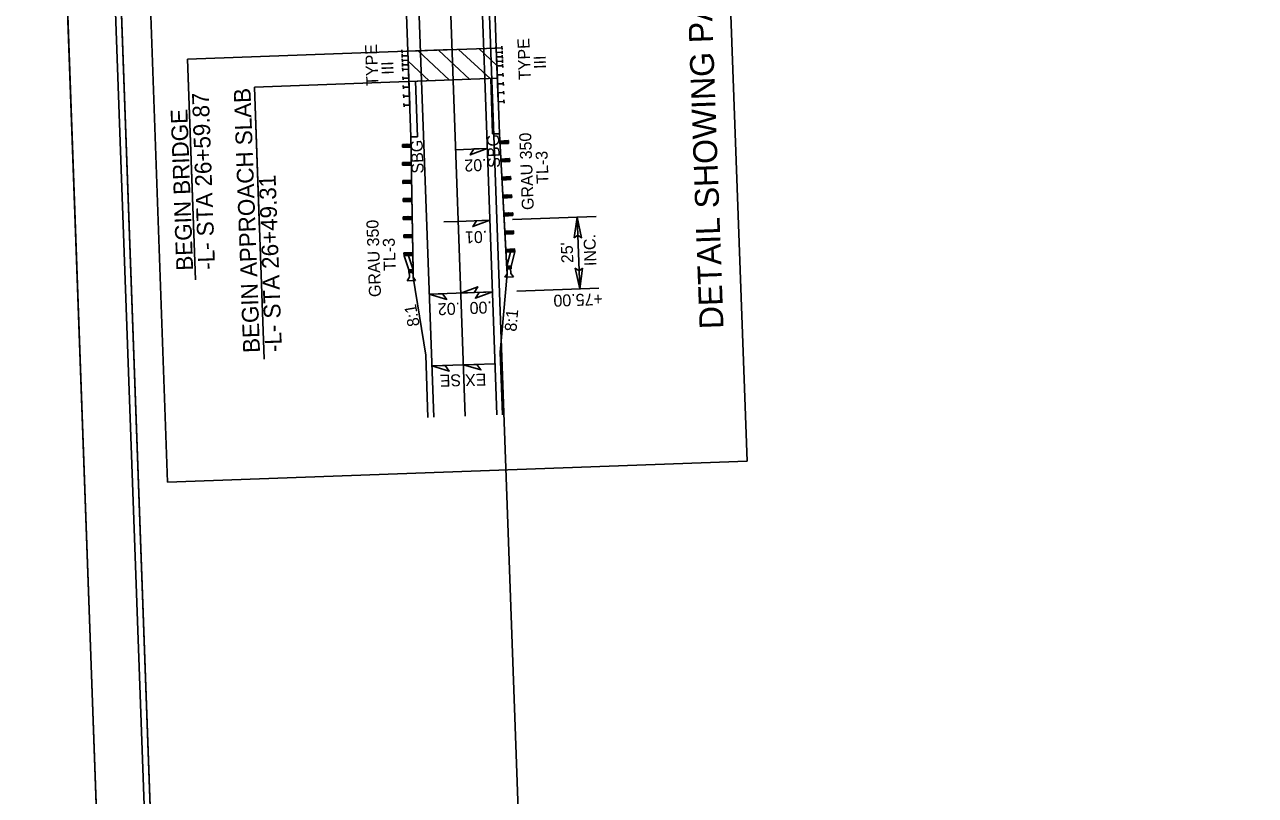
# Model space of a CAD drawing. Extents: x 2065256 to 2066537, y 145527 to 147314.
# Drawn here: x 2065382 to 2065896, y 146420 to 146742 of the extents above; entities that cross this region are included whole.
import ezdxf

# ---------------------------------------------------------------- set-up
doc = ezdxf.new("R2010")
doc.units = 0
for name, color, linetype in [('Prop Approach Slab', 7, 'Continuous'), ('Prop Approach Slab Hatching', 7, 'Continuous'), ('Prop Conc Shoulder Berm Gutter', 7, 'Continuous'), ('Prop Dimension', 7, 'Continuous'), ('Prop Dimension Text', 7, 'Continuous'), ('Prop EOT', 7, 'Continuous'), ('Prop Guardrail', 7, 'Continuous'), ('Prop Guardrail Anchor Unit CELL', 7, 'Continuous'), ('Prop Horizontal Alignment', 7, 'Continuous'), ('Prop Horizontal Alignment Station Label', 7, 'Continuous'), ('Prop Horizontal Alignment Tick Small', 7, 'Continuous'), ('Prop Paved Shoulder', 7, 'Continuous'), ('Prop Roadway Bridge', 7, 'Continuous'), ('Prop Structure Anchor Unit CELL', 7, 'Continuous'), ('Prop Superelevation  Arrow CELL', 7, 'Continuous'), ('Prop Superelevation Label', 7, 'Continuous'), ('Prop Terminator CELL', 7, 'Continuous'), ('Sheet Clip Boundary CELL', 7, 'Continuous'), ('Sheet Cutting Line CELL', 7, 'Continuous'), ('Sheet Layout Plan Border', 7, 'Continuous'), ('Sheet Plan CELL', 7, 'Continuous'), ('Sheet Plan Layout CELL', 7, 'Continuous'), ('Sheet Plot Border Inside CELL', 7, 'Continuous'), ('Sheet Plot Border Outside CELL', 7, 'Continuous')]:
    doc.layers.add(name, color=color, linetype=linetype)

# ---------------------------------------------------------------- blocks, each defined once
blk = doc.blocks.new('Super Arrow Terminator')
at = {"layer": 'Prop Superelevation  Arrow CELL'}
blk.add_lwpolyline([(0, 0), (-6, -2), (-4.625, 0)], close=True, dxfattribs=at)

msp = doc.modelspace()

# ---------------------------------------------------------------- linework, layer by layer
at = {"layer": 'Prop Approach Slab'}
for p, q in [((2065542.53, 146718.66), (2065542.07, 146731.33)), ((2065579.5, 146720), (2065579.04, 146732.66)), ((2065542.53, 146718.66), (2065579.5, 146720))]:
    msp.add_line(p, q, dxfattribs=at)
at = {"layer": 'Prop Approach Slab Hatching'}
for p, q in [((2065559.48, 146719.28), (2065546.36, 146731.48)), ((2065567.96, 146719.58), (2065554.84, 146731.79)), ((2065576.44, 146719.89), (2065563.32, 146732.1)), ((2065579.31, 146725.42), (2065571.8, 146732.4)), ((2065579.04, 146732.75), (2065578.58, 146733.18)), ((2065551.01, 146718.97), (2065542.22, 146727.14))]:
    msp.add_line(p, q, dxfattribs=at)
at = {"layer": 'Prop Conc Shoulder Berm Gutter'}
for p, q in [((2065546.16, 146695.61), (2065545.32, 146718.76)), ((2065577.54, 146696.74), (2065576.71, 146719.9))]:
    msp.add_line(p, q, dxfattribs=at)
at = {"layer": 'Prop Dimension'}
for p, q in [((2065683.84, 146559.92), (2065666.92, 147028.09)), ((2065441.7, 146551.17), (2065424.78, 147019.34)), ((2065620.8, 146662.28), (2065585.78, 146661.02)), ((2065613.91, 146632.01), (2065612.83, 146661.99)), ((2065621.88, 146632.3), (2065587.66, 146631.07)), ((2065683.84, 146559.92), (2065441.7, 146551.17))]:
    msp.add_line(p, q, dxfattribs=at)
at = {"layer": 'Prop EOT'}
for p, q in [((2065547.82, 146718.86), (2065537.68, 146999.49)), ((2065574.2, 146719.81), (2065564.06, 147000.44)), ((2065552.9, 146578.33), (2065547.82, 146719.01)), ((2065579.28, 146579.28), (2065574.2, 146719.96)), ((2065577.54, 146696.74), (2065580.34, 146696.84))]:
    msp.add_line(p, q, dxfattribs=at)
at = {"layer": 'Prop Guardrail'}
for p, q in [((2065542.81, 146710.8), (2065543.08, 146703.3)), ((2065580.06, 146704.64), (2065579.79, 146712.13))]:
    msp.add_line(p, q, dxfattribs=at)
at = {"layer": 'Prop Guardrail Anchor Unit CELL'}
for p, q in [((2065543.36, 146695.51), (2065544.27, 146639.41)), ((2065580.34, 146696.84), (2065583.49, 146640.83)), ((2065543.41, 146692.46), (2065539.81, 146692.4)), ((2065541.63, 146691.23), (2065539.81, 146692.4)), ((2065539.81, 146692.4), (2065539.83, 146691.2)), ((2065539.83, 146691.2), (2065541.61, 146692.43)), ((2065543.43, 146691.26), (2065539.83, 146691.2)), ((2065541.61, 146692.43), (2065541.63, 146691.23)), ((2065541.61, 146692.43), (2065543.43, 146691.26)), ((2065541.63, 146691.23), (2065543.41, 146692.46)), ((2065543.43, 146691.26), (2065541.63, 146691.23)), ((2065543.41, 146692.46), (2065543.43, 146691.26)), ((2065580.51, 146693.8), (2065584.1, 146694)), ((2065580.51, 146693.8), (2065580.58, 146692.6)), ((2065582.37, 146692.7), (2065580.51, 146693.8)), ((2065582.31, 146693.9), (2065580.58, 146692.6)), ((2065580.58, 146692.6), (2065584.17, 146692.8)), ((2065580.58, 146692.6), (2065582.37, 146692.7)), ((2065582.31, 146693.9), (2065582.37, 146692.7)), ((2065584.17, 146692.8), (2065582.31, 146693.9)), ((2065582.37, 146692.7), (2065584.1, 146694)), ((2065584.1, 146694), (2065584.17, 146692.8)), ((2065543.53, 146684.9), (2065539.87, 146684.84)), ((2065541.72, 146683.67), (2065539.87, 146684.84)), ((2065539.87, 146684.84), (2065539.89, 146683.64)), ((2065539.89, 146683.64), (2065541.7, 146684.87)), ((2065541.7, 146684.87), (2065541.72, 146683.67)), ((2065541.7, 146684.87), (2065543.55, 146683.7)), ((2065543.53, 146684.9), (2065541.72, 146683.67)), ((2065580.93, 146686.25), (2065584.59, 146686.45)), ((2065580.93, 146686.25), (2065582.83, 146685.15)), ((2065582.76, 146686.35), (2065581, 146685.05)), ((2065581, 146685.05), (2065584.66, 146685.25)), ((2065582.76, 146686.35), (2065582.83, 146685.15)), ((2065584.66, 146685.25), (2065582.76, 146686.35)), ((2065582.83, 146685.15), (2065584.59, 146686.45)), ((2065584.59, 146686.45), (2065584.66, 146685.25)), ((2065543.55, 146683.7), (2065539.89, 146683.64)), ((2065543.66, 146677.34), (2065540, 146677.28)), ((2065541.85, 146676.11), (2065540, 146677.28)), ((2065540, 146677.28), (2065540.02, 146676.08)), ((2065540.02, 146676.08), (2065541.83, 146677.31)), ((2065543.67, 146676.14), (2065540.02, 146676.08)), ((2065541.83, 146677.31), (2065541.85, 146676.11)), ((2065541.83, 146677.31), (2065543.67, 146676.14)), ((2065543.66, 146677.34), (2065541.85, 146676.11)), ((2065581.36, 146678.7), (2065585.01, 146678.9)), ((2065581.36, 146678.7), (2065583.25, 146677.6)), ((2065583.18, 146678.8), (2065581.43, 146677.5)), ((2065581.43, 146677.5), (2065585.08, 146677.71)), ((2065583.18, 146678.8), (2065583.25, 146677.6)), ((2065585.08, 146677.71), (2065583.18, 146678.8)), ((2065583.25, 146677.6), (2065585.01, 146678.9)), ((2065585.01, 146678.9), (2065585.08, 146677.71)), ((2065543.78, 146669.77), (2065540.14, 146669.72)), ((2065541.98, 146668.54), (2065540.14, 146669.72)), ((2065540.14, 146669.72), (2065540.15, 146668.52)), ((2065540.15, 146668.52), (2065541.96, 146669.75)), ((2065541.96, 146669.75), (2065541.98, 146668.54)), ((2065541.96, 146669.75), (2065543.8, 146668.57)), ((2065543.78, 146669.77), (2065541.98, 146668.54)), ((2065543.78, 146669.77), (2065543.8, 146668.57)), ((2065581.78, 146671.15), (2065585.42, 146671.35)), ((2065581.78, 146671.15), (2065581.85, 146669.95)), ((2065581.78, 146671.15), (2065583.67, 146670.05)), ((2065583.6, 146671.25), (2065581.85, 146669.95)), ((2065581.85, 146669.95), (2065585.49, 146670.15)), ((2065583.6, 146671.25), (2065583.67, 146670.05)), ((2065585.49, 146670.15), (2065583.6, 146671.25)), ((2065583.67, 146670.05), (2065585.42, 146671.35)), ((2065585.42, 146671.35), (2065585.49, 146670.15)), ((2065543.8, 146668.57), (2065540.15, 146668.52)), ((2065543.9, 146662.21), (2065540.13, 146662.15)), ((2065542.04, 146660.98), (2065540.13, 146662.15)), ((2065540.13, 146662.15), (2065540.15, 146660.95)), ((2065540.15, 146660.95), (2065542.02, 146662.18)), ((2065543.92, 146661.01), (2065540.15, 146660.95)), ((2065542.02, 146662.18), (2065542.04, 146660.98)), ((2065542.02, 146662.18), (2065543.92, 146661.01)), ((2065543.9, 146662.21), (2065542.04, 146660.98)), ((2065582.21, 146663.6), (2065585.97, 146663.81)), ((2065582.21, 146663.6), (2065584.15, 146662.51)), ((2065584.09, 146663.71), (2065582.27, 146662.4)), ((2065582.27, 146662.4), (2065586.03, 146662.61)), ((2065584.09, 146663.71), (2065584.15, 146662.51)), ((2065586.03, 146662.61), (2065584.09, 146663.71)), ((2065584.15, 146662.51), (2065585.97, 146663.81)), ((2065585.97, 146663.81), (2065586.03, 146662.61)), ((2065544.02, 146654.65), (2065540.42, 146654.6)), ((2065542.24, 146653.42), (2065540.42, 146654.6)), ((2065540.42, 146654.6), (2065540.44, 146653.4)), ((2065540.44, 146653.4), (2065542.22, 146654.62)), ((2065542.22, 146654.62), (2065542.24, 146653.42)), ((2065542.22, 146654.62), (2065544.04, 146653.45)), ((2065544.02, 146654.65), (2065542.24, 146653.42)), ((2065582.63, 146656.05), (2065586.22, 146656.25)), ((2065582.63, 146656.05), (2065584.5, 146654.95)), ((2065584.43, 146656.15), (2065582.7, 146654.85)), ((2065582.7, 146654.85), (2065586.29, 146655.05)), ((2065584.43, 146656.15), (2065584.5, 146654.95)), ((2065586.29, 146655.05), (2065584.43, 146656.15)), ((2065584.5, 146654.95), (2065586.22, 146656.25)), ((2065586.22, 146656.25), (2065586.29, 146655.05)), ((2065544.04, 146653.45), (2065540.44, 146653.4)), ((2065583.05, 146648.5), (2065586.73, 146648.71)), ((2065584.89, 146648.6), (2065583.12, 146647.3)), ((2065584.89, 146648.6), (2065584.96, 146647.4)), ((2065586.79, 146647.51), (2065584.89, 146648.6)), ((2065584.96, 146647.4), (2065586.73, 146648.71)), ((2065586.73, 146648.71), (2065586.79, 146647.51)), ((2065544.14, 146647.09), (2065540.47, 146647.03)), ((2065542.32, 146645.86), (2065540.47, 146647.03)), ((2065540.47, 146647.03), (2065540.49, 146645.83)), ((2065540.49, 146645.83), (2065542.31, 146647.06)), ((2065544.16, 146645.89), (2065540.49, 146645.83)), ((2065540.49, 146645.83), (2065542.46, 146639.98)), ((2065542.31, 146647.06), (2065542.32, 146645.86)), ((2065542.31, 146647.06), (2065544.16, 146645.89)), ((2065544.14, 146647.09), (2065542.32, 146645.86)), ((2065542.32, 146645.86), (2065544.26, 146640.01)), ((2065583.05, 146648.5), (2065584.96, 146647.4)), ((2065583.12, 146647.3), (2065586.79, 146647.51)), ((2065584.96, 146647.4), (2065583.45, 146641.43)), ((2065586.79, 146647.51), (2065585.25, 146641.53)), ((2065544.26, 146640.01), (2065542.46, 146639.98)), ((2065542.46, 146639.98), (2065542.47, 146639.38)), ((2065544.28, 146638.81), (2065542.46, 146639.98)), ((2065542.46, 146639.98), (2065542.48, 146638.78)), ((2065542.48, 146638.78), (2065544.26, 146640.01)), ((2065544.28, 146638.81), (2065542.48, 146638.78)), ((2065542.71, 146639.32), (2065543.44, 146639.35)), ((2065542.8, 146636.87), (2065542.71, 146639.32)), ((2065543.44, 146639.35), (2065544.18, 146639.37)), ((2065544.18, 146639.37), (2065544.26, 146636.92)), ((2065583.67, 146638.34), (2065582.69, 146636.89)), ((2065583.45, 146641.43), (2065585.25, 146641.53)), ((2065585.32, 146640.33), (2065583.45, 146641.43)), ((2065583.52, 146640.23), (2065585.25, 146641.53)), ((2065583.52, 146640.23), (2065585.32, 146640.33)), ((2065584.31, 146640.83), (2065583.58, 146640.8)), ((2065583.58, 146640.8), (2065583.67, 146638.34)), ((2065585.04, 146640.85), (2065584.31, 146640.83)), ((2065585.14, 146638.4), (2065585.04, 146640.85)), ((2065586.22, 146637.03), (2065585.14, 146638.4)), ((2065585.25, 146641.53), (2065585.28, 146640.93)), ((2065585.25, 146641.53), (2065585.32, 146640.33)), ((2065541.82, 146635.42), (2065542.8, 146636.87)), ((2065545.34, 146635.54), (2065541.82, 146635.42)), ((2065544.26, 146636.92), (2065545.34, 146635.54)), ((2065582.69, 146636.89), (2065586.22, 146637.03))]:
    msp.add_line(p, q, dxfattribs=at)
at = {"layer": 'Prop Horizontal Alignment'}
msp.add_line((2065566.09, 146578.81), (2065550.87, 146999.96), dxfattribs=at)
at = {"layer": 'Prop Horizontal Alignment Station Label'}
for p, q in [((2065560.56, 146732), (2065450.04, 146728)), ((2065450.04, 146728), (2065452.69, 146654.75)), ((2065450.04, 146728), (2065453.38, 146635.8)), ((2065561.01, 146719.33), (2065477.97, 146716.33)), ((2065477.97, 146716.33), (2065480.13, 146656.56)), ((2065477.97, 146716.33), (2065482.08, 146602.64))]:
    msp.add_line(p, q, dxfattribs=at)
at = {"layer": 'Prop Horizontal Alignment Tick Small'}
msp.add_line((2065563.15, 146660.2), (2065557.15, 146659.98), dxfattribs=at)
at = {"layer": 'Prop Paved Shoulder'}
for p, q in [((2065543.36, 146695.51), (2065542.52, 146718.82)), ((2065580.34, 146696.84), (2065579.5, 146720.16)), ((2065543.36, 146695.51), (2065546.16, 146695.61)), ((2065580.74, 146605.48), (2065583.67, 146638.34)), ((2065549.56, 146604.35), (2065544.26, 146636.92)), ((2065550.5, 146578.24), (2065549.56, 146604.35)), ((2065581.68, 146579.37), (2065580.74, 146605.48))]:
    msp.add_line(p, q, dxfattribs=at)
for points in [[(2065544.26, 146636.92), (2065544.28, 146638.81), (2065543.36, 146695.51)], [(2065583.67, 146638.34), (2065583.52, 146640.23), (2065580.34, 146696.84)]]:
    msp.add_lwpolyline(points, dxfattribs=at)
at = {"layer": 'Prop Roadway Bridge'}
for p, q in [((2065542.07, 146731.33), (2065538.24, 146837.17)), ((2065579.04, 146732.66), (2065575.22, 146838.51)), ((2065579.04, 146732.66), (2065542.07, 146731.33))]:
    msp.add_line(p, q, dxfattribs=at)
at = {"layer": 'Prop Structure Anchor Unit CELL'}
for p, q in [((2065539.64, 146731.93), (2065539.69, 146730.55)), ((2065542.07, 146731.33), (2065539.67, 146731.24)), ((2065542.07, 146731.33), (2065542.88, 146708.84)), ((2065579.04, 146732.66), (2065581.44, 146732.75)), ((2065579.04, 146732.66), (2065579.86, 146710.18)), ((2065579.11, 146730.79), (2065581.51, 146730.88)), ((2065581.42, 146733.44), (2065581.47, 146732.06)), ((2065581.48, 146731.56), (2065581.53, 146730.19)), ((2065539.71, 146730.05), (2065539.76, 146728.68)), ((2065542.14, 146729.45), (2065539.74, 146729.37)), ((2065539.78, 146728.18), (2065539.83, 146726.81)), ((2065542.2, 146727.58), (2065539.8, 146727.49)), ((2065539.85, 146726.31), (2065539.9, 146724.93)), ((2065542.27, 146725.71), (2065539.87, 146725.62)), ((2065579.18, 146728.92), (2065581.58, 146729)), ((2065579.25, 146727.04), (2065581.64, 146727.13)), ((2065581.55, 146729.69), (2065581.6, 146728.32)), ((2065581.62, 146727.82), (2065581.67, 146726.44)), ((2065581.69, 146725.94), (2065581.74, 146724.57)), ((2065539.92, 146724.43), (2065539.96, 146723.06)), ((2065542.34, 146723.83), (2065539.94, 146723.75)), ((2065540.05, 146720.68), (2065540.1, 146719.31)), ((2065579.31, 146725.17), (2065581.71, 146725.26)), ((2065579.45, 146721.42), (2065581.85, 146721.51)), ((2065581.82, 146722.19), (2065581.87, 146720.82)), ((2065542.47, 146720.08), (2065540.08, 146720)), ((2065540.19, 146716.94), (2065540.24, 146715.56)), ((2065542.61, 146716.34), (2065540.21, 146716.25)), ((2065579.59, 146717.67), (2065581.98, 146717.76)), ((2065581.96, 146718.45), (2065582.01, 146717.07)), ((2065540.32, 146713.19), (2065540.37, 146711.82)), ((2065542.74, 146712.59), (2065540.35, 146712.5)), ((2065579.72, 146713.93), (2065582.12, 146714.01)), ((2065579.86, 146710.18), (2065582.25, 146710.27)), ((2065582.09, 146714.7), (2065582.14, 146713.33)), ((2065582.23, 146710.95), (2065582.28, 146709.58)), ((2065540.46, 146709.44), (2065540.51, 146708.07)), ((2065542.88, 146708.84), (2065540.48, 146708.76))]:
    msp.add_line(p, q, dxfattribs=at)
at = {"layer": 'Prop Superelevation  Arrow CELL'}
for p, q in [((2065562.07, 146690.18), (2065575.26, 146690.66)), ((2065563.15, 146660.2), (2065576.34, 146660.68)), ((2065551.04, 146629.74), (2065577.43, 146630.7)), ((2065552.13, 146599.76), (2065578.51, 146600.71))]:
    msp.add_line(p, q, dxfattribs=at)
at = {"layer": 'Prop Terminator CELL'}
for points in [[(2065611.65, 146653.31), (2065612.83, 146661.99), (2065614.68, 146653.37), (2065613.1, 146654.42)], [(2065615.09, 146640.7), (2065613.91, 146632.01), (2065612.06, 146640.64), (2065613.64, 146639.59)]]:
    msp.add_lwpolyline(points, close=True, dxfattribs=at)
at = {"layer": 'Sheet Clip Boundary CELL'}
msp.add_lwpolyline([(2066225.3, 145855.32), (2066356.28, 145860.05), (2066306.24, 147244.42), (2065582.18, 147218.25), (2065589.94, 147003.52), (2065566.99, 147001.07), (2065609.27, 145831.43)], close=True, dxfattribs=at)
at = {"layer": 'Sheet Cutting Line CELL'}
msp.add_line((2065381.93, 147244.73), (2065442.74, 145562.33), dxfattribs=at)
at = {"layer": 'Sheet Layout Plan Border'}
msp.add_lwpolyline([(2066506.71, 145817.42), (2066456.14, 147216.52), (2065618.17, 147186.22), (2065625.01, 146997.09), (2065413.66, 146989.45), (2065457.4, 145779.49)], close=True, dxfattribs=at)
at = {"layer": 'Sheet Plan CELL'}
for points in [[(2065405.01, 147228.58), (2065459.2, 145729.52), (2066508.52, 145767.45), (2066454.33, 147266.48)], [(2066508.52, 145767.45), (2065459.23, 145729.49), (2065412.23, 147028.63), (2065562.19, 147034.07), (2065554.98, 147233.97), (2066454.33, 147266.48)]]:
    msp.add_lwpolyline(points, close=True, dxfattribs=at)
at = {"layer": 'Sheet Plan Layout CELL'}
msp.add_lwpolyline([(2065459.23, 145729.49), (2066508.52, 145767.45), (2066454.33, 147266.47), (2065616.37, 147236.18), (2065625.01, 146997.09), (2065413.66, 146989.45)], close=True, dxfattribs=at)
at = {"layer": 'Sheet Plot Border Inside CELL'}
msp.add_lwpolyline([(2066516.57, 145614.15), (2066456.38, 147279.05), (2065402.08, 147240.95), (2065462.26, 145576.04)], close=True, dxfattribs=at)
at = {"layer": 'Sheet Plot Border Outside CELL'}
msp.add_lwpolyline([(2066537.03, 145601.88), (2066476.21, 147284.29), (2065381.93, 147244.73), (2065442.74, 145562.33)], close=True, dxfattribs=at)

# ---------------------------------------------------------------- block references
at = {"layer": 'Prop Superelevation  Arrow CELL'}
for p, xscale, yscale, rotation in [((2065575.26, 146690.66), 1.1999976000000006, 1.199997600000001, 2.070244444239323), ((2065576.34, 146660.68), 1.1999976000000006, 1.199997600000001, 2.070244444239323), ((2065551.04, 146629.74), 1.1999976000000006, -1.1999976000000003, -177.9297555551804), ((2065564.23, 146630.22), 1.1999976, 1.199997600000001, -177.92975555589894), ((2065577.43, 146630.7), 1.1999976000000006, 1.199997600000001, 2.070244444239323), ((2065552.13, 146599.76), 1.1999976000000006, -1.1999976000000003, -177.9297555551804), ((2065565.32, 146600.24), 1.1999976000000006, -1.1999976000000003, -177.9297555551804)]:
    msp.add_blockref('Super Arrow Terminator', p, dxfattribs=dict(at, xscale=xscale, yscale=yscale, rotation=rotation))

# ---------------------------------------------------------------- texts
at = {"layer": 'Prop Dimension'}
msp.add_text('DETAIL SHOWING PAVEMENT AND BRIDGE RELATIONSHIP', height=10, rotation=92.0702, dxfattribs=at).set_placement((2065674.05, 146615.35))
at = {"layer": 'Prop Dimension Text'}
for s, rotation, p in [('SBG', 92.0702, (2065580.66, 146682.66)), ('SBG', 92.0702, (2065548.72, 146680.3)), ('INC.', 92.0702, (2065620.93, 146641.61)), ("25'", 92.0702, (2065611.28, 146642.84)), ('+75.00', 182.0702, (2065623.48, 146630.25)), ('8:1', 100.0087, (2065547.06, 146616.69)), ('8:1', 84.9938, (2065587.46, 146613.99))]:
    msp.add_text(s, height=5, rotation=rotation, dxfattribs=at).set_placement(p)
at = {"layer": 'Prop Guardrail Anchor Unit CELL'}
for s, p in [('GRAU 350', (2065594.77, 146665.05)), ('TL-3', (2065600.94, 146676)), ('GRAU 350', (2065530.9, 146628.66)), ('TL-3', (2065537.06, 146639.61))]:
    msp.add_text(s, height=5, rotation=92.0702, dxfattribs=at).set_placement(p)
at = {"layer": 'Prop Horizontal Alignment Station Label'}
for s, p in [('BEGIN APPROACH SLAB', (2065480.31, 146605.35)), ('-L- STA 26+59.87', (2065461.55, 146640.06)), ('BEGIN BRIDGE', (2065452.37, 146639.73)), ('-L- STA 26+49.31', (2065489.48, 146605.68))]:
    msp.add_text(s, height=7, rotation=92.0702, dxfattribs=at).set_placement(p)
at = {"layer": 'Prop Structure Anchor Unit CELL'}
for s, p in [('TYPE', (2065593.47, 146719.41)), ('TYPE', (2065529.79, 146716.98)), ('III', (2065536.18, 146721.61)), ('III', (2065599.86, 146724.04))]:
    msp.add_text(s, height=5, rotation=92.0702, dxfattribs=at).set_placement(p)
at = {"layer": 'Prop Superelevation Label'}
for s, rotation, p in [('.02', 182.0702, (2065574.92, 146686.33)), ('.01', 182.0702, (2065575.18, 146656.29)), ('.02', 182.0702, (2065563.84, 146626.28)), ('.00', 182.0702, (2065577.11, 146626.79)), ('SE', 181.7804, (2065564.29, 146596.34)), ('EX', 181.7804, (2065574.82, 146596.59))]:
    msp.add_text(s, height=5, rotation=rotation, dxfattribs=at).set_placement(p)

doc.saveas('drawing.dxf')
